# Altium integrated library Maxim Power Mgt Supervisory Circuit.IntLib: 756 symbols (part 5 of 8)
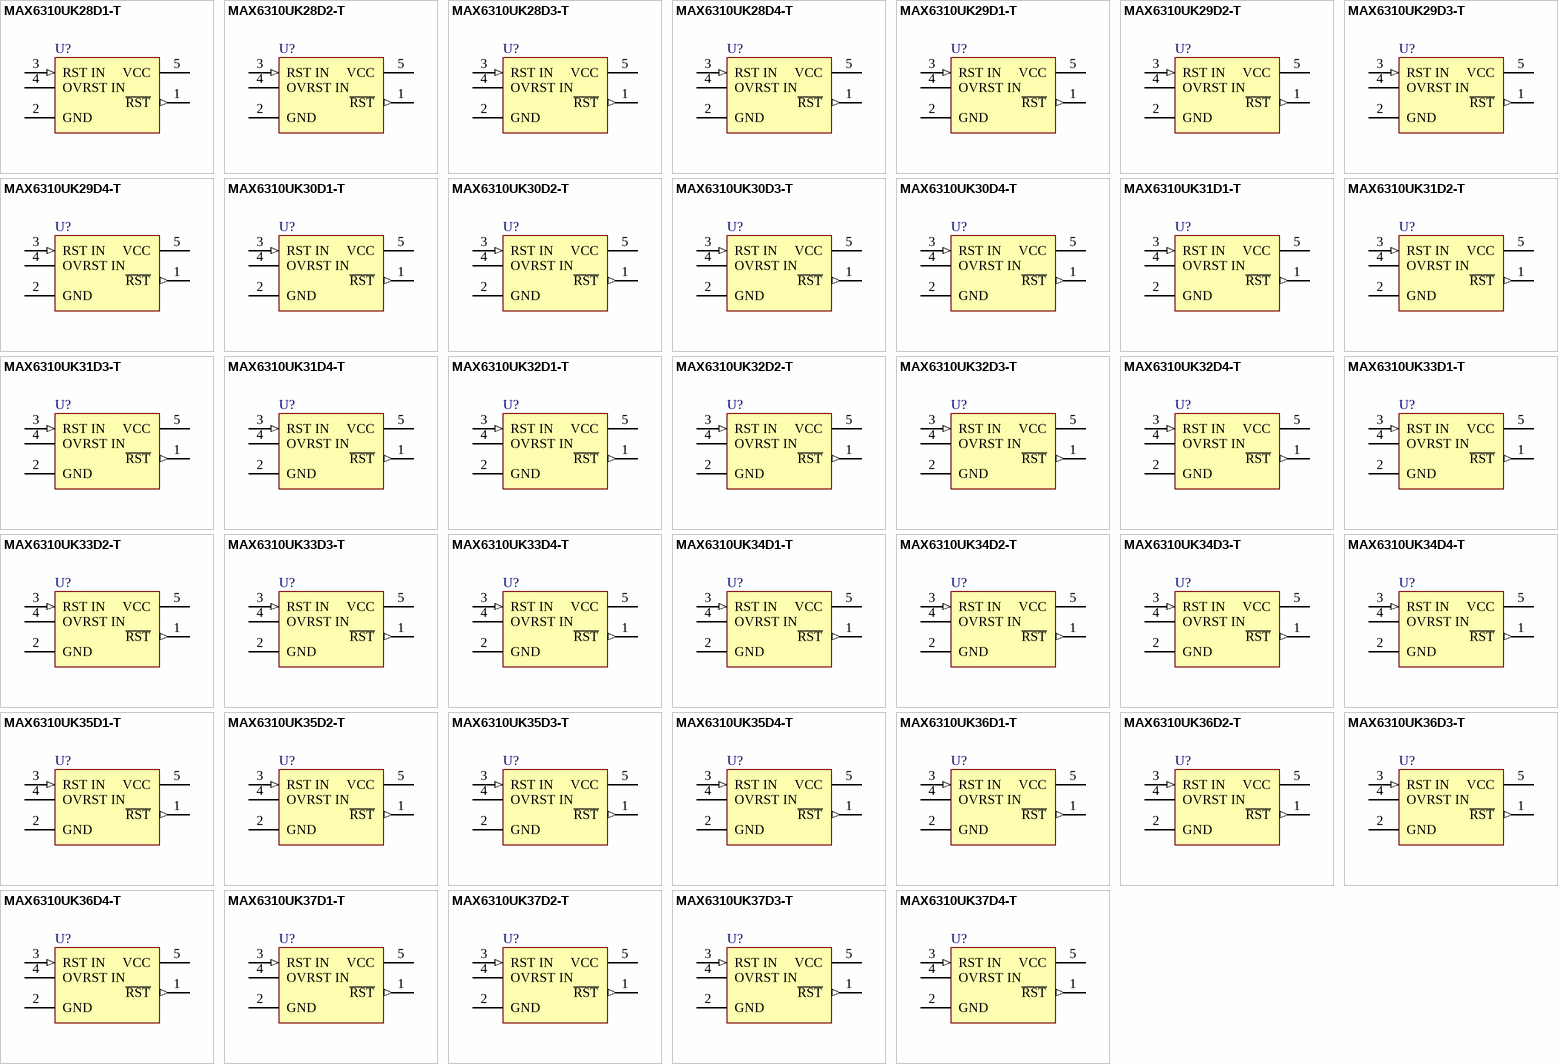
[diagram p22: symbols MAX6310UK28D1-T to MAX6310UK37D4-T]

## MAX6310UK36D1-T
designator U?
5-Pin, Multiple-Input, Programmable Reset IC
footprint SOT23-5_N (SOT23, 5-Leads, Body 2.9x1.6mm, Pitch 0.95mm, Lead Span 2.8mm, IPC Medium Density)
footprint SOT23-5_L (SOT23, 5-Leads, Body 2.9x1.6mm, Pitch 0.95mm, Lead Span 2.8mm, IPC High Density)
footprint SOT23-5_M (SOT23, 5-Leads, Body 2.9x1.6mm, Pitch 0.95mm, Lead Span 2.8mm, IPC Low Density)
pins: 1 ~{RST} (out), 2 GND (power), 3 RST IN (in), 4 OVRST IN, 5 VCC (power)

## MAX6310UK36D2-T
designator U?
5-Pin, Multiple-Input, Programmable Reset IC
footprint SOT23-5_N (SOT23, 5-Leads, Body 2.9x1.6mm, Pitch 0.95mm, Lead Span 2.8mm, IPC Medium Density)
footprint SOT23-5_L (SOT23, 5-Leads, Body 2.9x1.6mm, Pitch 0.95mm, Lead Span 2.8mm, IPC High Density)
footprint SOT23-5_M (SOT23, 5-Leads, Body 2.9x1.6mm, Pitch 0.95mm, Lead Span 2.8mm, IPC Low Density)
pins: 1 ~{RST} (out), 2 GND (power), 3 RST IN (in), 4 OVRST IN, 5 VCC (power)

## MAX6310UK36D3-T
designator U?
5-Pin, Multiple-Input, Programmable Reset IC
footprint SOT23-5_N (SOT23, 5-Leads, Body 2.9x1.6mm, Pitch 0.95mm, Lead Span 2.8mm, IPC Medium Density)
footprint SOT23-5_L (SOT23, 5-Leads, Body 2.9x1.6mm, Pitch 0.95mm, Lead Span 2.8mm, IPC High Density)
footprint SOT23-5_M (SOT23, 5-Leads, Body 2.9x1.6mm, Pitch 0.95mm, Lead Span 2.8mm, IPC Low Density)
pins: 1 ~{RST} (out), 2 GND (power), 3 RST IN (in), 4 OVRST IN, 5 VCC (power)

## MAX6310UK36D4-T
designator U?
5-Pin, Multiple-Input, Programmable Reset IC
footprint SOT23-5_N (SOT23, 5-Leads, Body 2.9x1.6mm, Pitch 0.95mm, Lead Span 2.8mm, IPC Medium Density)
footprint SOT23-5_L (SOT23, 5-Leads, Body 2.9x1.6mm, Pitch 0.95mm, Lead Span 2.8mm, IPC High Density)
footprint SOT23-5_M (SOT23, 5-Leads, Body 2.9x1.6mm, Pitch 0.95mm, Lead Span 2.8mm, IPC Low Density)
pins: 1 ~{RST} (out), 2 GND (power), 3 RST IN (in), 4 OVRST IN, 5 VCC (power)

## MAX6310UK37D1-T
designator U?
5-Pin, Multiple-Input, Programmable Reset IC
footprint SOT23-5_N (SOT23, 5-Leads, Body 2.9x1.6mm, Pitch 0.95mm, Lead Span 2.8mm, IPC Medium Density)
footprint SOT23-5_L (SOT23, 5-Leads, Body 2.9x1.6mm, Pitch 0.95mm, Lead Span 2.8mm, IPC High Density)
footprint SOT23-5_M (SOT23, 5-Leads, Body 2.9x1.6mm, Pitch 0.95mm, Lead Span 2.8mm, IPC Low Density)
pins: 1 ~{RST} (out), 2 GND (power), 3 RST IN (in), 4 OVRST IN, 5 VCC (power)

## MAX6310UK37D2-T
designator U?
5-Pin, Multiple-Input, Programmable Reset IC
footprint SOT23-5_N (SOT23, 5-Leads, Body 2.9x1.6mm, Pitch 0.95mm, Lead Span 2.8mm, IPC Medium Density)
footprint SOT23-5_L (SOT23, 5-Leads, Body 2.9x1.6mm, Pitch 0.95mm, Lead Span 2.8mm, IPC High Density)
footprint SOT23-5_M (SOT23, 5-Leads, Body 2.9x1.6mm, Pitch 0.95mm, Lead Span 2.8mm, IPC Low Density)
pins: 1 ~{RST} (out), 2 GND (power), 3 RST IN (in), 4 OVRST IN, 5 VCC (power)

## MAX6310UK37D3-T
designator U?
5-Pin, Multiple-Input, Programmable Reset IC
footprint SOT23-5_N (SOT23, 5-Leads, Body 2.9x1.6mm, Pitch 0.95mm, Lead Span 2.8mm, IPC Medium Density)
footprint SOT23-5_L (SOT23, 5-Leads, Body 2.9x1.6mm, Pitch 0.95mm, Lead Span 2.8mm, IPC High Density)
footprint SOT23-5_M (SOT23, 5-Leads, Body 2.9x1.6mm, Pitch 0.95mm, Lead Span 2.8mm, IPC Low Density)
pins: 1 ~{RST} (out), 2 GND (power), 3 RST IN (in), 4 OVRST IN, 5 VCC (power)

## MAX6310UK37D4-T
designator U?
5-Pin, Multiple-Input, Programmable Reset IC
footprint SOT23-5_N (SOT23, 5-Leads, Body 2.9x1.6mm, Pitch 0.95mm, Lead Span 2.8mm, IPC Medium Density)
footprint SOT23-5_L (SOT23, 5-Leads, Body 2.9x1.6mm, Pitch 0.95mm, Lead Span 2.8mm, IPC High Density)
footprint SOT23-5_M (SOT23, 5-Leads, Body 2.9x1.6mm, Pitch 0.95mm, Lead Span 2.8mm, IPC Low Density)
pins: 1 ~{RST} (out), 2 GND (power), 3 RST IN (in), 4 OVRST IN, 5 VCC (power)

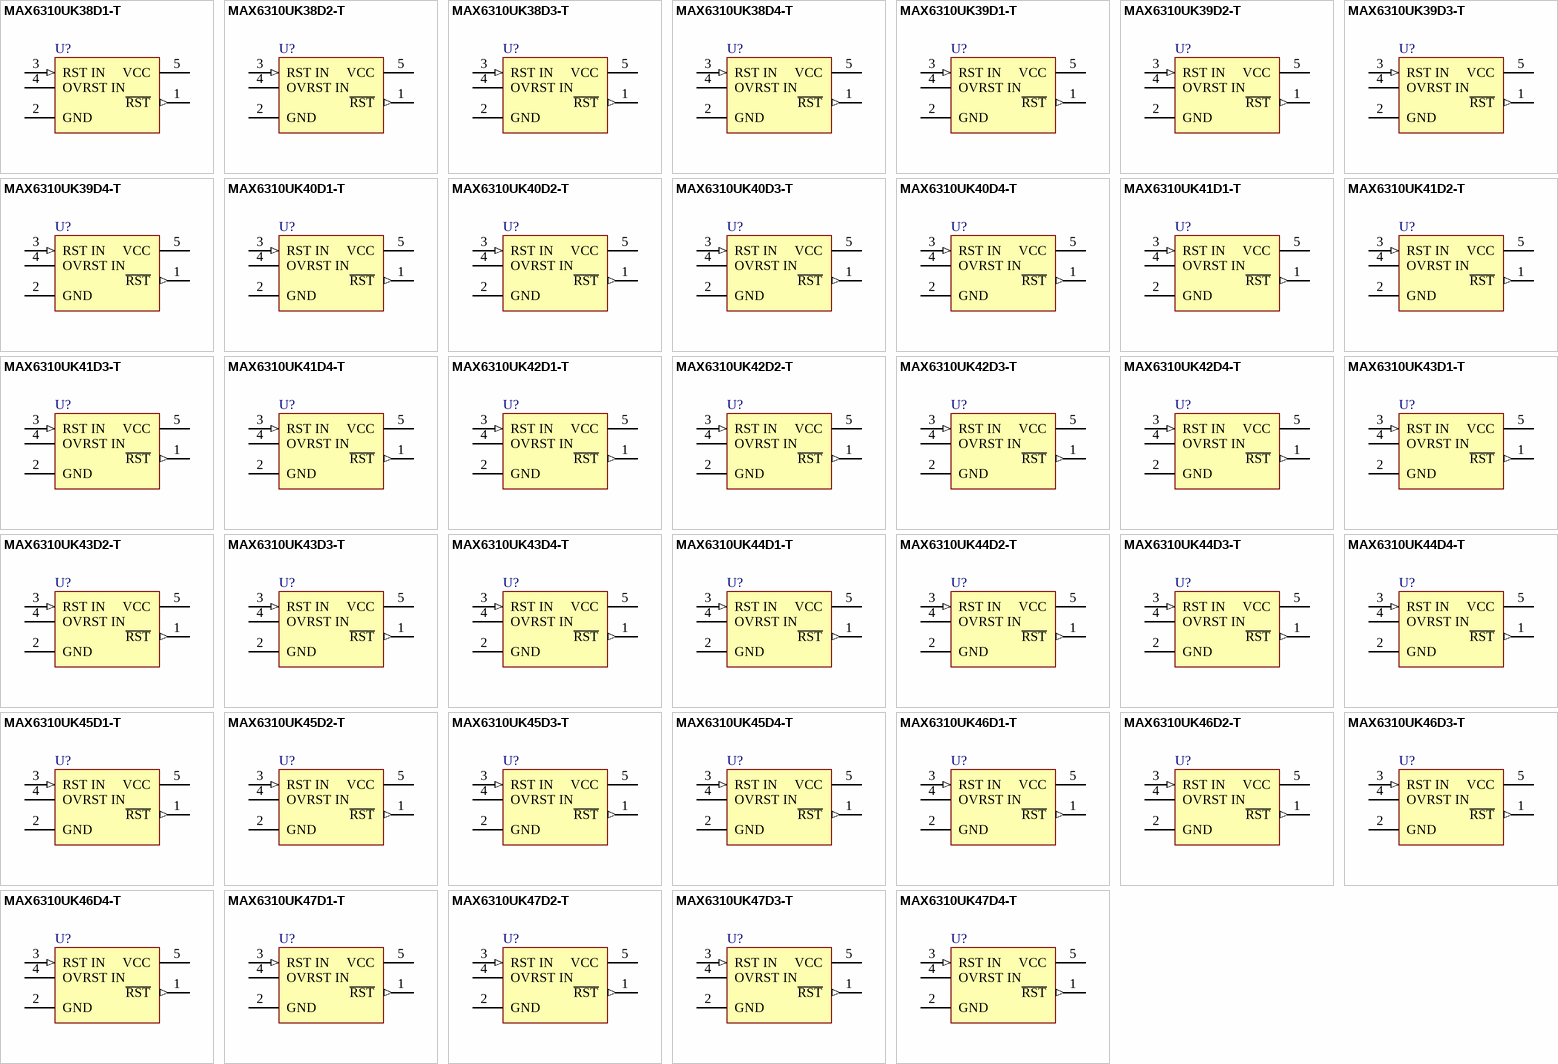
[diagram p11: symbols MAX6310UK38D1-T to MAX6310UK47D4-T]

## MAX6310UK38D1-T
designator U?
5-Pin, Multiple-Input, Programmable Reset IC
footprint SOT23-5_N (SOT23, 5-Leads, Body 2.9x1.6mm, Pitch 0.95mm, Lead Span 2.8mm, IPC Medium Density)
footprint SOT23-5_L (SOT23, 5-Leads, Body 2.9x1.6mm, Pitch 0.95mm, Lead Span 2.8mm, IPC High Density)
footprint SOT23-5_M (SOT23, 5-Leads, Body 2.9x1.6mm, Pitch 0.95mm, Lead Span 2.8mm, IPC Low Density)
pins: 1 ~{RST} (out), 2 GND (power), 3 RST IN (in), 4 OVRST IN, 5 VCC (power)

## MAX6310UK38D2-T
designator U?
5-Pin, Multiple-Input, Programmable Reset IC
footprint SOT23-5_N (SOT23, 5-Leads, Body 2.9x1.6mm, Pitch 0.95mm, Lead Span 2.8mm, IPC Medium Density)
footprint SOT23-5_L (SOT23, 5-Leads, Body 2.9x1.6mm, Pitch 0.95mm, Lead Span 2.8mm, IPC High Density)
footprint SOT23-5_M (SOT23, 5-Leads, Body 2.9x1.6mm, Pitch 0.95mm, Lead Span 2.8mm, IPC Low Density)
pins: 1 ~{RST} (out), 2 GND (power), 3 RST IN (in), 4 OVRST IN, 5 VCC (power)

## MAX6310UK38D3-T
designator U?
5-Pin, Multiple-Input, Programmable Reset IC
footprint SOT23-5_N (SOT23, 5-Leads, Body 2.9x1.6mm, Pitch 0.95mm, Lead Span 2.8mm, IPC Medium Density)
footprint SOT23-5_L (SOT23, 5-Leads, Body 2.9x1.6mm, Pitch 0.95mm, Lead Span 2.8mm, IPC High Density)
footprint SOT23-5_M (SOT23, 5-Leads, Body 2.9x1.6mm, Pitch 0.95mm, Lead Span 2.8mm, IPC Low Density)
pins: 1 ~{RST} (out), 2 GND (power), 3 RST IN (in), 4 OVRST IN, 5 VCC (power)

## MAX6310UK38D4-T
designator U?
5-Pin, Multiple-Input, Programmable Reset IC
footprint SOT23-5_N (SOT23, 5-Leads, Body 2.9x1.6mm, Pitch 0.95mm, Lead Span 2.8mm, IPC Medium Density)
footprint SOT23-5_L (SOT23, 5-Leads, Body 2.9x1.6mm, Pitch 0.95mm, Lead Span 2.8mm, IPC High Density)
footprint SOT23-5_M (SOT23, 5-Leads, Body 2.9x1.6mm, Pitch 0.95mm, Lead Span 2.8mm, IPC Low Density)
pins: 1 ~{RST} (out), 2 GND (power), 3 RST IN (in), 4 OVRST IN, 5 VCC (power)

## MAX6310UK39D1-T
designator U?
5-Pin, Multiple-Input, Programmable Reset IC
footprint SOT23-5_N (SOT23, 5-Leads, Body 2.9x1.6mm, Pitch 0.95mm, Lead Span 2.8mm, IPC Medium Density)
footprint SOT23-5_L (SOT23, 5-Leads, Body 2.9x1.6mm, Pitch 0.95mm, Lead Span 2.8mm, IPC High Density)
footprint SOT23-5_M (SOT23, 5-Leads, Body 2.9x1.6mm, Pitch 0.95mm, Lead Span 2.8mm, IPC Low Density)
pins: 1 ~{RST} (out), 2 GND (power), 3 RST IN (in), 4 OVRST IN, 5 VCC (power)

## MAX6310UK39D2-T
designator U?
5-Pin, Multiple-Input, Programmable Reset IC
footprint SOT23-5_N (SOT23, 5-Leads, Body 2.9x1.6mm, Pitch 0.95mm, Lead Span 2.8mm, IPC Medium Density)
footprint SOT23-5_L (SOT23, 5-Leads, Body 2.9x1.6mm, Pitch 0.95mm, Lead Span 2.8mm, IPC High Density)
footprint SOT23-5_M (SOT23, 5-Leads, Body 2.9x1.6mm, Pitch 0.95mm, Lead Span 2.8mm, IPC Low Density)
pins: 1 ~{RST} (out), 2 GND (power), 3 RST IN (in), 4 OVRST IN, 5 VCC (power)

## MAX6310UK39D3-T
designator U?
5-Pin, Multiple-Input, Programmable Reset IC
footprint SOT23-5_N (SOT23, 5-Leads, Body 2.9x1.6mm, Pitch 0.95mm, Lead Span 2.8mm, IPC Medium Density)
footprint SOT23-5_L (SOT23, 5-Leads, Body 2.9x1.6mm, Pitch 0.95mm, Lead Span 2.8mm, IPC High Density)
footprint SOT23-5_M (SOT23, 5-Leads, Body 2.9x1.6mm, Pitch 0.95mm, Lead Span 2.8mm, IPC Low Density)
pins: 1 ~{RST} (out), 2 GND (power), 3 RST IN (in), 4 OVRST IN, 5 VCC (power)

## MAX6310UK39D4-T
designator U?
5-Pin, Multiple-Input, Programmable Reset IC
footprint SOT23-5_N (SOT23, 5-Leads, Body 2.9x1.6mm, Pitch 0.95mm, Lead Span 2.8mm, IPC Medium Density)
footprint SOT23-5_L (SOT23, 5-Leads, Body 2.9x1.6mm, Pitch 0.95mm, Lead Span 2.8mm, IPC High Density)
footprint SOT23-5_M (SOT23, 5-Leads, Body 2.9x1.6mm, Pitch 0.95mm, Lead Span 2.8mm, IPC Low Density)
pins: 1 ~{RST} (out), 2 GND (power), 3 RST IN (in), 4 OVRST IN, 5 VCC (power)

## MAX6310UK40D1-T
designator U?
5-Pin, Multiple-Input, Programmable Reset IC
footprint SOT23-5_N (SOT23, 5-Leads, Body 2.9x1.6mm, Pitch 0.95mm, Lead Span 2.8mm, IPC Medium Density)
footprint SOT23-5_L (SOT23, 5-Leads, Body 2.9x1.6mm, Pitch 0.95mm, Lead Span 2.8mm, IPC High Density)
footprint SOT23-5_M (SOT23, 5-Leads, Body 2.9x1.6mm, Pitch 0.95mm, Lead Span 2.8mm, IPC Low Density)
pins: 1 ~{RST} (out), 2 GND (power), 3 RST IN (in), 4 OVRST IN, 5 VCC (power)

## MAX6310UK40D2-T
designator U?
5-Pin, Multiple-Input, Programmable Reset IC
footprint SOT23-5_N (SOT23, 5-Leads, Body 2.9x1.6mm, Pitch 0.95mm, Lead Span 2.8mm, IPC Medium Density)
footprint SOT23-5_L (SOT23, 5-Leads, Body 2.9x1.6mm, Pitch 0.95mm, Lead Span 2.8mm, IPC High Density)
footprint SOT23-5_M (SOT23, 5-Leads, Body 2.9x1.6mm, Pitch 0.95mm, Lead Span 2.8mm, IPC Low Density)
pins: 1 ~{RST} (out), 2 GND (power), 3 RST IN (in), 4 OVRST IN, 5 VCC (power)

## MAX6310UK40D3-T
designator U?
5-Pin, Multiple-Input, Programmable Reset IC
footprint SOT23-5_N (SOT23, 5-Leads, Body 2.9x1.6mm, Pitch 0.95mm, Lead Span 2.8mm, IPC Medium Density)
footprint SOT23-5_L (SOT23, 5-Leads, Body 2.9x1.6mm, Pitch 0.95mm, Lead Span 2.8mm, IPC High Density)
footprint SOT23-5_M (SOT23, 5-Leads, Body 2.9x1.6mm, Pitch 0.95mm, Lead Span 2.8mm, IPC Low Density)
pins: 1 ~{RST} (out), 2 GND (power), 3 RST IN (in), 4 OVRST IN, 5 VCC (power)

## MAX6310UK40D4-T
designator U?
5-Pin, Multiple-Input, Programmable Reset IC
footprint SOT23-5_N (SOT23, 5-Leads, Body 2.9x1.6mm, Pitch 0.95mm, Lead Span 2.8mm, IPC Medium Density)
footprint SOT23-5_L (SOT23, 5-Leads, Body 2.9x1.6mm, Pitch 0.95mm, Lead Span 2.8mm, IPC High Density)
footprint SOT23-5_M (SOT23, 5-Leads, Body 2.9x1.6mm, Pitch 0.95mm, Lead Span 2.8mm, IPC Low Density)
pins: 1 ~{RST} (out), 2 GND (power), 3 RST IN (in), 4 OVRST IN, 5 VCC (power)

## MAX6310UK41D1-T
designator U?
5-Pin, Multiple-Input, Programmable Reset IC
footprint SOT23-5_N (SOT23, 5-Leads, Body 2.9x1.6mm, Pitch 0.95mm, Lead Span 2.8mm, IPC Medium Density)
footprint SOT23-5_L (SOT23, 5-Leads, Body 2.9x1.6mm, Pitch 0.95mm, Lead Span 2.8mm, IPC High Density)
footprint SOT23-5_M (SOT23, 5-Leads, Body 2.9x1.6mm, Pitch 0.95mm, Lead Span 2.8mm, IPC Low Density)
pins: 1 ~{RST} (out), 2 GND (power), 3 RST IN (in), 4 OVRST IN, 5 VCC (power)

## MAX6310UK41D2-T
designator U?
5-Pin, Multiple-Input, Programmable Reset IC
footprint SOT23-5_N (SOT23, 5-Leads, Body 2.9x1.6mm, Pitch 0.95mm, Lead Span 2.8mm, IPC Medium Density)
footprint SOT23-5_L (SOT23, 5-Leads, Body 2.9x1.6mm, Pitch 0.95mm, Lead Span 2.8mm, IPC High Density)
footprint SOT23-5_M (SOT23, 5-Leads, Body 2.9x1.6mm, Pitch 0.95mm, Lead Span 2.8mm, IPC Low Density)
pins: 1 ~{RST} (out), 2 GND (power), 3 RST IN (in), 4 OVRST IN, 5 VCC (power)

## MAX6310UK41D3-T
designator U?
5-Pin, Multiple-Input, Programmable Reset IC
footprint SOT23-5_N (SOT23, 5-Leads, Body 2.9x1.6mm, Pitch 0.95mm, Lead Span 2.8mm, IPC Medium Density)
footprint SOT23-5_L (SOT23, 5-Leads, Body 2.9x1.6mm, Pitch 0.95mm, Lead Span 2.8mm, IPC High Density)
footprint SOT23-5_M (SOT23, 5-Leads, Body 2.9x1.6mm, Pitch 0.95mm, Lead Span 2.8mm, IPC Low Density)
pins: 1 ~{RST} (out), 2 GND (power), 3 RST IN (in), 4 OVRST IN, 5 VCC (power)

## MAX6310UK41D4-T
designator U?
5-Pin, Multiple-Input, Programmable Reset IC
footprint SOT23-5_N (SOT23, 5-Leads, Body 2.9x1.6mm, Pitch 0.95mm, Lead Span 2.8mm, IPC Medium Density)
footprint SOT23-5_L (SOT23, 5-Leads, Body 2.9x1.6mm, Pitch 0.95mm, Lead Span 2.8mm, IPC High Density)
footprint SOT23-5_M (SOT23, 5-Leads, Body 2.9x1.6mm, Pitch 0.95mm, Lead Span 2.8mm, IPC Low Density)
pins: 1 ~{RST} (out), 2 GND (power), 3 RST IN (in), 4 OVRST IN, 5 VCC (power)

## MAX6310UK42D1-T
designator U?
5-Pin, Multiple-Input, Programmable Reset IC
footprint SOT23-5_N (SOT23, 5-Leads, Body 2.9x1.6mm, Pitch 0.95mm, Lead Span 2.8mm, IPC Medium Density)
footprint SOT23-5_L (SOT23, 5-Leads, Body 2.9x1.6mm, Pitch 0.95mm, Lead Span 2.8mm, IPC High Density)
footprint SOT23-5_M (SOT23, 5-Leads, Body 2.9x1.6mm, Pitch 0.95mm, Lead Span 2.8mm, IPC Low Density)
pins: 1 ~{RST} (out), 2 GND (power), 3 RST IN (in), 4 OVRST IN, 5 VCC (power)

## MAX6310UK42D2-T
designator U?
5-Pin, Multiple-Input, Programmable Reset IC
footprint SOT23-5_N (SOT23, 5-Leads, Body 2.9x1.6mm, Pitch 0.95mm, Lead Span 2.8mm, IPC Medium Density)
footprint SOT23-5_L (SOT23, 5-Leads, Body 2.9x1.6mm, Pitch 0.95mm, Lead Span 2.8mm, IPC High Density)
footprint SOT23-5_M (SOT23, 5-Leads, Body 2.9x1.6mm, Pitch 0.95mm, Lead Span 2.8mm, IPC Low Density)
pins: 1 ~{RST} (out), 2 GND (power), 3 RST IN (in), 4 OVRST IN, 5 VCC (power)

## MAX6310UK42D3-T
designator U?
5-Pin, Multiple-Input, Programmable Reset IC
footprint SOT23-5_N (SOT23, 5-Leads, Body 2.9x1.6mm, Pitch 0.95mm, Lead Span 2.8mm, IPC Medium Density)
footprint SOT23-5_L (SOT23, 5-Leads, Body 2.9x1.6mm, Pitch 0.95mm, Lead Span 2.8mm, IPC High Density)
footprint SOT23-5_M (SOT23, 5-Leads, Body 2.9x1.6mm, Pitch 0.95mm, Lead Span 2.8mm, IPC Low Density)
pins: 1 ~{RST} (out), 2 GND (power), 3 RST IN (in), 4 OVRST IN, 5 VCC (power)

## MAX6310UK42D4-T
designator U?
5-Pin, Multiple-Input, Programmable Reset IC
footprint SOT23-5_N (SOT23, 5-Leads, Body 2.9x1.6mm, Pitch 0.95mm, Lead Span 2.8mm, IPC Medium Density)
footprint SOT23-5_L (SOT23, 5-Leads, Body 2.9x1.6mm, Pitch 0.95mm, Lead Span 2.8mm, IPC High Density)
footprint SOT23-5_M (SOT23, 5-Leads, Body 2.9x1.6mm, Pitch 0.95mm, Lead Span 2.8mm, IPC Low Density)
pins: 1 ~{RST} (out), 2 GND (power), 3 RST IN (in), 4 OVRST IN, 5 VCC (power)

## MAX6310UK43D1-T
designator U?
5-Pin, Multiple-Input, Programmable Reset IC
footprint SOT23-5_N (SOT23, 5-Leads, Body 2.9x1.6mm, Pitch 0.95mm, Lead Span 2.8mm, IPC Medium Density)
footprint SOT23-5_L (SOT23, 5-Leads, Body 2.9x1.6mm, Pitch 0.95mm, Lead Span 2.8mm, IPC High Density)
footprint SOT23-5_M (SOT23, 5-Leads, Body 2.9x1.6mm, Pitch 0.95mm, Lead Span 2.8mm, IPC Low Density)
pins: 1 ~{RST} (out), 2 GND (power), 3 RST IN (in), 4 OVRST IN, 5 VCC (power)

## MAX6310UK43D2-T
designator U?
5-Pin, Multiple-Input, Programmable Reset IC
footprint SOT23-5_N (SOT23, 5-Leads, Body 2.9x1.6mm, Pitch 0.95mm, Lead Span 2.8mm, IPC Medium Density)
footprint SOT23-5_L (SOT23, 5-Leads, Body 2.9x1.6mm, Pitch 0.95mm, Lead Span 2.8mm, IPC High Density)
footprint SOT23-5_M (SOT23, 5-Leads, Body 2.9x1.6mm, Pitch 0.95mm, Lead Span 2.8mm, IPC Low Density)
pins: 1 ~{RST} (out), 2 GND (power), 3 RST IN (in), 4 OVRST IN, 5 VCC (power)

## MAX6310UK43D3-T
designator U?
5-Pin, Multiple-Input, Programmable Reset IC
footprint SOT23-5_N (SOT23, 5-Leads, Body 2.9x1.6mm, Pitch 0.95mm, Lead Span 2.8mm, IPC Medium Density)
footprint SOT23-5_L (SOT23, 5-Leads, Body 2.9x1.6mm, Pitch 0.95mm, Lead Span 2.8mm, IPC High Density)
footprint SOT23-5_M (SOT23, 5-Leads, Body 2.9x1.6mm, Pitch 0.95mm, Lead Span 2.8mm, IPC Low Density)
pins: 1 ~{RST} (out), 2 GND (power), 3 RST IN (in), 4 OVRST IN, 5 VCC (power)

## MAX6310UK43D4-T
designator U?
5-Pin, Multiple-Input, Programmable Reset IC
footprint SOT23-5_N (SOT23, 5-Leads, Body 2.9x1.6mm, Pitch 0.95mm, Lead Span 2.8mm, IPC Medium Density)
footprint SOT23-5_L (SOT23, 5-Leads, Body 2.9x1.6mm, Pitch 0.95mm, Lead Span 2.8mm, IPC High Density)
footprint SOT23-5_M (SOT23, 5-Leads, Body 2.9x1.6mm, Pitch 0.95mm, Lead Span 2.8mm, IPC Low Density)
pins: 1 ~{RST} (out), 2 GND (power), 3 RST IN (in), 4 OVRST IN, 5 VCC (power)

## MAX6310UK44D1-T
designator U?
5-Pin, Multiple-Input, Programmable Reset IC
footprint SOT23-5_N (SOT23, 5-Leads, Body 2.9x1.6mm, Pitch 0.95mm, Lead Span 2.8mm, IPC Medium Density)
footprint SOT23-5_L (SOT23, 5-Leads, Body 2.9x1.6mm, Pitch 0.95mm, Lead Span 2.8mm, IPC High Density)
footprint SOT23-5_M (SOT23, 5-Leads, Body 2.9x1.6mm, Pitch 0.95mm, Lead Span 2.8mm, IPC Low Density)
pins: 1 ~{RST} (out), 2 GND (power), 3 RST IN (in), 4 OVRST IN, 5 VCC (power)

## MAX6310UK44D2-T
designator U?
5-Pin, Multiple-Input, Programmable Reset IC
footprint SOT23-5_N (SOT23, 5-Leads, Body 2.9x1.6mm, Pitch 0.95mm, Lead Span 2.8mm, IPC Medium Density)
footprint SOT23-5_L (SOT23, 5-Leads, Body 2.9x1.6mm, Pitch 0.95mm, Lead Span 2.8mm, IPC High Density)
footprint SOT23-5_M (SOT23, 5-Leads, Body 2.9x1.6mm, Pitch 0.95mm, Lead Span 2.8mm, IPC Low Density)
pins: 1 ~{RST} (out), 2 GND (power), 3 RST IN (in), 4 OVRST IN, 5 VCC (power)

## MAX6310UK44D3-T
designator U?
5-Pin, Multiple-Input, Programmable Reset IC
footprint SOT23-5_N (SOT23, 5-Leads, Body 2.9x1.6mm, Pitch 0.95mm, Lead Span 2.8mm, IPC Medium Density)
footprint SOT23-5_L (SOT23, 5-Leads, Body 2.9x1.6mm, Pitch 0.95mm, Lead Span 2.8mm, IPC High Density)
footprint SOT23-5_M (SOT23, 5-Leads, Body 2.9x1.6mm, Pitch 0.95mm, Lead Span 2.8mm, IPC Low Density)
pins: 1 ~{RST} (out), 2 GND (power), 3 RST IN (in), 4 OVRST IN, 5 VCC (power)

## MAX6310UK44D4-T
designator U?
5-Pin, Multiple-Input, Programmable Reset IC
footprint SOT23-5_N (SOT23, 5-Leads, Body 2.9x1.6mm, Pitch 0.95mm, Lead Span 2.8mm, IPC Medium Density)
footprint SOT23-5_L (SOT23, 5-Leads, Body 2.9x1.6mm, Pitch 0.95mm, Lead Span 2.8mm, IPC High Density)
footprint SOT23-5_M (SOT23, 5-Leads, Body 2.9x1.6mm, Pitch 0.95mm, Lead Span 2.8mm, IPC Low Density)
pins: 1 ~{RST} (out), 2 GND (power), 3 RST IN (in), 4 OVRST IN, 5 VCC (power)

## MAX6310UK45D1-T
designator U?
5-Pin, Multiple-Input, Programmable Reset IC
footprint SOT23-5_N (SOT23, 5-Leads, Body 2.9x1.6mm, Pitch 0.95mm, Lead Span 2.8mm, IPC Medium Density)
footprint SOT23-5_L (SOT23, 5-Leads, Body 2.9x1.6mm, Pitch 0.95mm, Lead Span 2.8mm, IPC High Density)
footprint SOT23-5_M (SOT23, 5-Leads, Body 2.9x1.6mm, Pitch 0.95mm, Lead Span 2.8mm, IPC Low Density)
pins: 1 ~{RST} (out), 2 GND (power), 3 RST IN (in), 4 OVRST IN, 5 VCC (power)

## MAX6310UK45D2-T
designator U?
5-Pin, Multiple-Input, Programmable Reset IC
footprint SOT23-5_N (SOT23, 5-Leads, Body 2.9x1.6mm, Pitch 0.95mm, Lead Span 2.8mm, IPC Medium Density)
footprint SOT23-5_L (SOT23, 5-Leads, Body 2.9x1.6mm, Pitch 0.95mm, Lead Span 2.8mm, IPC High Density)
footprint SOT23-5_M (SOT23, 5-Leads, Body 2.9x1.6mm, Pitch 0.95mm, Lead Span 2.8mm, IPC Low Density)
pins: 1 ~{RST} (out), 2 GND (power), 3 RST IN (in), 4 OVRST IN, 5 VCC (power)

## MAX6310UK45D3-T
designator U?
5-Pin, Multiple-Input, Programmable Reset IC
footprint SOT23-5_N (SOT23, 5-Leads, Body 2.9x1.6mm, Pitch 0.95mm, Lead Span 2.8mm, IPC Medium Density)
footprint SOT23-5_L (SOT23, 5-Leads, Body 2.9x1.6mm, Pitch 0.95mm, Lead Span 2.8mm, IPC High Density)
footprint SOT23-5_M (SOT23, 5-Leads, Body 2.9x1.6mm, Pitch 0.95mm, Lead Span 2.8mm, IPC Low Density)
pins: 1 ~{RST} (out), 2 GND (power), 3 RST IN (in), 4 OVRST IN, 5 VCC (power)

## MAX6310UK45D4-T
designator U?
5-Pin, Multiple-Input, Programmable Reset IC
footprint SOT23-5_N (SOT23, 5-Leads, Body 2.9x1.6mm, Pitch 0.95mm, Lead Span 2.8mm, IPC Medium Density)
footprint SOT23-5_L (SOT23, 5-Leads, Body 2.9x1.6mm, Pitch 0.95mm, Lead Span 2.8mm, IPC High Density)
footprint SOT23-5_M (SOT23, 5-Leads, Body 2.9x1.6mm, Pitch 0.95mm, Lead Span 2.8mm, IPC Low Density)
pins: 1 ~{RST} (out), 2 GND (power), 3 RST IN (in), 4 OVRST IN, 5 VCC (power)

## MAX6310UK46D1-T
designator U?
5-Pin, Multiple-Input, Programmable Reset IC
footprint SOT23-5_N (SOT23, 5-Leads, Body 2.9x1.6mm, Pitch 0.95mm, Lead Span 2.8mm, IPC Medium Density)
footprint SOT23-5_L (SOT23, 5-Leads, Body 2.9x1.6mm, Pitch 0.95mm, Lead Span 2.8mm, IPC High Density)
footprint SOT23-5_M (SOT23, 5-Leads, Body 2.9x1.6mm, Pitch 0.95mm, Lead Span 2.8mm, IPC Low Density)
pins: 1 ~{RST} (out), 2 GND (power), 3 RST IN (in), 4 OVRST IN, 5 VCC (power)

## MAX6310UK46D2-T
designator U?
5-Pin, Multiple-Input, Programmable Reset IC
footprint SOT23-5_N (SOT23, 5-Leads, Body 2.9x1.6mm, Pitch 0.95mm, Lead Span 2.8mm, IPC Medium Density)
footprint SOT23-5_L (SOT23, 5-Leads, Body 2.9x1.6mm, Pitch 0.95mm, Lead Span 2.8mm, IPC High Density)
footprint SOT23-5_M (SOT23, 5-Leads, Body 2.9x1.6mm, Pitch 0.95mm, Lead Span 2.8mm, IPC Low Density)
pins: 1 ~{RST} (out), 2 GND (power), 3 RST IN (in), 4 OVRST IN, 5 VCC (power)

## MAX6310UK46D3-T
designator U?
5-Pin, Multiple-Input, Programmable Reset IC
footprint SOT23-5_N (SOT23, 5-Leads, Body 2.9x1.6mm, Pitch 0.95mm, Lead Span 2.8mm, IPC Medium Density)
footprint SOT23-5_L (SOT23, 5-Leads, Body 2.9x1.6mm, Pitch 0.95mm, Lead Span 2.8mm, IPC High Density)
footprint SOT23-5_M (SOT23, 5-Leads, Body 2.9x1.6mm, Pitch 0.95mm, Lead Span 2.8mm, IPC Low Density)
pins: 1 ~{RST} (out), 2 GND (power), 3 RST IN (in), 4 OVRST IN, 5 VCC (power)

## MAX6310UK46D4-T
designator U?
5-Pin, Multiple-Input, Programmable Reset IC
footprint SOT23-5_N (SOT23, 5-Leads, Body 2.9x1.6mm, Pitch 0.95mm, Lead Span 2.8mm, IPC Medium Density)
footprint SOT23-5_L (SOT23, 5-Leads, Body 2.9x1.6mm, Pitch 0.95mm, Lead Span 2.8mm, IPC High Density)
footprint SOT23-5_M (SOT23, 5-Leads, Body 2.9x1.6mm, Pitch 0.95mm, Lead Span 2.8mm, IPC Low Density)
pins: 1 ~{RST} (out), 2 GND (power), 3 RST IN (in), 4 OVRST IN, 5 VCC (power)

## MAX6310UK47D1-T
designator U?
5-Pin, Multiple-Input, Programmable Reset IC
footprint SOT23-5_N (SOT23, 5-Leads, Body 2.9x1.6mm, Pitch 0.95mm, Lead Span 2.8mm, IPC Medium Density)
footprint SOT23-5_L (SOT23, 5-Leads, Body 2.9x1.6mm, Pitch 0.95mm, Lead Span 2.8mm, IPC High Density)
footprint SOT23-5_M (SOT23, 5-Leads, Body 2.9x1.6mm, Pitch 0.95mm, Lead Span 2.8mm, IPC Low Density)
pins: 1 ~{RST} (out), 2 GND (power), 3 RST IN (in), 4 OVRST IN, 5 VCC (power)

## MAX6310UK47D2-T
designator U?
5-Pin, Multiple-Input, Programmable Reset IC
footprint SOT23-5_N (SOT23, 5-Leads, Body 2.9x1.6mm, Pitch 0.95mm, Lead Span 2.8mm, IPC Medium Density)
footprint SOT23-5_L (SOT23, 5-Leads, Body 2.9x1.6mm, Pitch 0.95mm, Lead Span 2.8mm, IPC High Density)
footprint SOT23-5_M (SOT23, 5-Leads, Body 2.9x1.6mm, Pitch 0.95mm, Lead Span 2.8mm, IPC Low Density)
pins: 1 ~{RST} (out), 2 GND (power), 3 RST IN (in), 4 OVRST IN, 5 VCC (power)

## MAX6310UK47D3-T
designator U?
5-Pin, Multiple-Input, Programmable Reset IC
footprint SOT23-5_N (SOT23, 5-Leads, Body 2.9x1.6mm, Pitch 0.95mm, Lead Span 2.8mm, IPC Medium Density)
footprint SOT23-5_L (SOT23, 5-Leads, Body 2.9x1.6mm, Pitch 0.95mm, Lead Span 2.8mm, IPC High Density)
footprint SOT23-5_M (SOT23, 5-Leads, Body 2.9x1.6mm, Pitch 0.95mm, Lead Span 2.8mm, IPC Low Density)
pins: 1 ~{RST} (out), 2 GND (power), 3 RST IN (in), 4 OVRST IN, 5 VCC (power)

## MAX6310UK47D4-T
designator U?
5-Pin, Multiple-Input, Programmable Reset IC
footprint SOT23-5_N (SOT23, 5-Leads, Body 2.9x1.6mm, Pitch 0.95mm, Lead Span 2.8mm, IPC Medium Density)
footprint SOT23-5_L (SOT23, 5-Leads, Body 2.9x1.6mm, Pitch 0.95mm, Lead Span 2.8mm, IPC High Density)
footprint SOT23-5_M (SOT23, 5-Leads, Body 2.9x1.6mm, Pitch 0.95mm, Lead Span 2.8mm, IPC Low Density)
pins: 1 ~{RST} (out), 2 GND (power), 3 RST IN (in), 4 OVRST IN, 5 VCC (power)

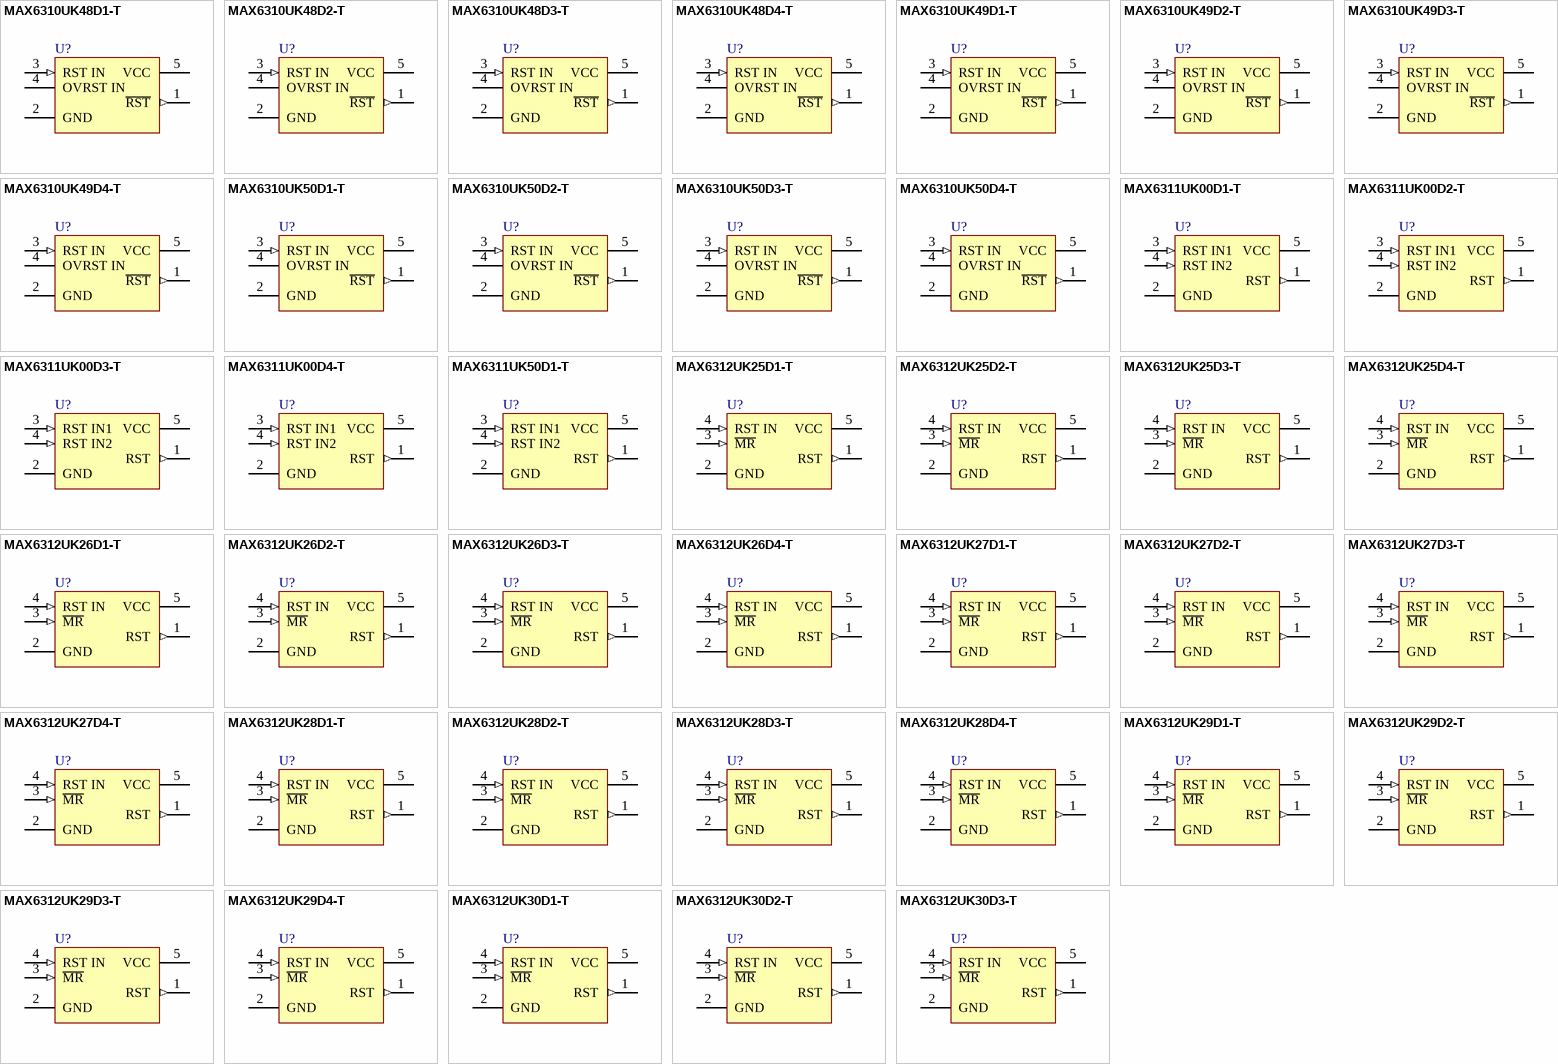
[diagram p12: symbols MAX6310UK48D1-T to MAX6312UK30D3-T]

## MAX6310UK48D1-T
designator U?
5-Pin, Multiple-Input, Programmable Reset IC
footprint SOT23-5_N (SOT23, 5-Leads, Body 2.9x1.6mm, Pitch 0.95mm, Lead Span 2.8mm, IPC Medium Density)
footprint SOT23-5_L (SOT23, 5-Leads, Body 2.9x1.6mm, Pitch 0.95mm, Lead Span 2.8mm, IPC High Density)
footprint SOT23-5_M (SOT23, 5-Leads, Body 2.9x1.6mm, Pitch 0.95mm, Lead Span 2.8mm, IPC Low Density)
pins: 1 ~{RST} (out), 2 GND (power), 3 RST IN (in), 4 OVRST IN, 5 VCC (power)

## MAX6310UK48D2-T
designator U?
5-Pin, Multiple-Input, Programmable Reset IC
footprint SOT23-5_N (SOT23, 5-Leads, Body 2.9x1.6mm, Pitch 0.95mm, Lead Span 2.8mm, IPC Medium Density)
footprint SOT23-5_L (SOT23, 5-Leads, Body 2.9x1.6mm, Pitch 0.95mm, Lead Span 2.8mm, IPC High Density)
footprint SOT23-5_M (SOT23, 5-Leads, Body 2.9x1.6mm, Pitch 0.95mm, Lead Span 2.8mm, IPC Low Density)
pins: 1 ~{RST} (out), 2 GND (power), 3 RST IN (in), 4 OVRST IN, 5 VCC (power)

## MAX6310UK48D3-T
designator U?
5-Pin, Multiple-Input, Programmable Reset IC
footprint SOT23-5_N (SOT23, 5-Leads, Body 2.9x1.6mm, Pitch 0.95mm, Lead Span 2.8mm, IPC Medium Density)
footprint SOT23-5_L (SOT23, 5-Leads, Body 2.9x1.6mm, Pitch 0.95mm, Lead Span 2.8mm, IPC High Density)
footprint SOT23-5_M (SOT23, 5-Leads, Body 2.9x1.6mm, Pitch 0.95mm, Lead Span 2.8mm, IPC Low Density)
pins: 1 ~{RST} (out), 2 GND (power), 3 RST IN (in), 4 OVRST IN, 5 VCC (power)

## MAX6310UK48D4-T
designator U?
5-Pin, Multiple-Input, Programmable Reset IC
footprint SOT23-5_N (SOT23, 5-Leads, Body 2.9x1.6mm, Pitch 0.95mm, Lead Span 2.8mm, IPC Medium Density)
footprint SOT23-5_L (SOT23, 5-Leads, Body 2.9x1.6mm, Pitch 0.95mm, Lead Span 2.8mm, IPC High Density)
footprint SOT23-5_M (SOT23, 5-Leads, Body 2.9x1.6mm, Pitch 0.95mm, Lead Span 2.8mm, IPC Low Density)
pins: 1 ~{RST} (out), 2 GND (power), 3 RST IN (in), 4 OVRST IN, 5 VCC (power)

## MAX6310UK49D1-T
designator U?
5-Pin, Multiple-Input, Programmable Reset IC
footprint SOT23-5_N (SOT23, 5-Leads, Body 2.9x1.6mm, Pitch 0.95mm, Lead Span 2.8mm, IPC Medium Density)
footprint SOT23-5_L (SOT23, 5-Leads, Body 2.9x1.6mm, Pitch 0.95mm, Lead Span 2.8mm, IPC High Density)
footprint SOT23-5_M (SOT23, 5-Leads, Body 2.9x1.6mm, Pitch 0.95mm, Lead Span 2.8mm, IPC Low Density)
pins: 1 ~{RST} (out), 2 GND (power), 3 RST IN (in), 4 OVRST IN, 5 VCC (power)

## MAX6310UK49D2-T
designator U?
5-Pin, Multiple-Input, Programmable Reset IC
footprint SOT23-5_N (SOT23, 5-Leads, Body 2.9x1.6mm, Pitch 0.95mm, Lead Span 2.8mm, IPC Medium Density)
footprint SOT23-5_L (SOT23, 5-Leads, Body 2.9x1.6mm, Pitch 0.95mm, Lead Span 2.8mm, IPC High Density)
footprint SOT23-5_M (SOT23, 5-Leads, Body 2.9x1.6mm, Pitch 0.95mm, Lead Span 2.8mm, IPC Low Density)
pins: 1 ~{RST} (out), 2 GND (power), 3 RST IN (in), 4 OVRST IN, 5 VCC (power)

## MAX6310UK49D3-T
designator U?
5-Pin, Multiple-Input, Programmable Reset IC
footprint SOT23-5_N (SOT23, 5-Leads, Body 2.9x1.6mm, Pitch 0.95mm, Lead Span 2.8mm, IPC Medium Density)
footprint SOT23-5_L (SOT23, 5-Leads, Body 2.9x1.6mm, Pitch 0.95mm, Lead Span 2.8mm, IPC High Density)
footprint SOT23-5_M (SOT23, 5-Leads, Body 2.9x1.6mm, Pitch 0.95mm, Lead Span 2.8mm, IPC Low Density)
pins: 1 ~{RST} (out), 2 GND (power), 3 RST IN (in), 4 OVRST IN, 5 VCC (power)

## MAX6310UK49D4-T
designator U?
5-Pin, Multiple-Input, Programmable Reset IC
footprint SOT23-5_N (SOT23, 5-Leads, Body 2.9x1.6mm, Pitch 0.95mm, Lead Span 2.8mm, IPC Medium Density)
footprint SOT23-5_L (SOT23, 5-Leads, Body 2.9x1.6mm, Pitch 0.95mm, Lead Span 2.8mm, IPC High Density)
footprint SOT23-5_M (SOT23, 5-Leads, Body 2.9x1.6mm, Pitch 0.95mm, Lead Span 2.8mm, IPC Low Density)
pins: 1 ~{RST} (out), 2 GND (power), 3 RST IN (in), 4 OVRST IN, 5 VCC (power)

## MAX6310UK50D1-T
designator U?
5-Pin, Multiple-Input, Programmable Reset IC
footprint SOT23-5_N (SOT23, 5-Leads, Body 2.9x1.6mm, Pitch 0.95mm, Lead Span 2.8mm, IPC Medium Density)
footprint SOT23-5_L (SOT23, 5-Leads, Body 2.9x1.6mm, Pitch 0.95mm, Lead Span 2.8mm, IPC High Density)
footprint SOT23-5_M (SOT23, 5-Leads, Body 2.9x1.6mm, Pitch 0.95mm, Lead Span 2.8mm, IPC Low Density)
pins: 1 ~{RST} (out), 2 GND (power), 3 RST IN (in), 4 OVRST IN, 5 VCC (power)

## MAX6310UK50D2-T
designator U?
5-Pin, Multiple-Input, Programmable Reset IC
footprint SOT23-5_N (SOT23, 5-Leads, Body 2.9x1.6mm, Pitch 0.95mm, Lead Span 2.8mm, IPC Medium Density)
footprint SOT23-5_L (SOT23, 5-Leads, Body 2.9x1.6mm, Pitch 0.95mm, Lead Span 2.8mm, IPC High Density)
footprint SOT23-5_M (SOT23, 5-Leads, Body 2.9x1.6mm, Pitch 0.95mm, Lead Span 2.8mm, IPC Low Density)
pins: 1 ~{RST} (out), 2 GND (power), 3 RST IN (in), 4 OVRST IN, 5 VCC (power)

## MAX6310UK50D3-T
designator U?
5-Pin, Multiple-Input, Programmable Reset IC
footprint SOT23-5_N (SOT23, 5-Leads, Body 2.9x1.6mm, Pitch 0.95mm, Lead Span 2.8mm, IPC Medium Density)
footprint SOT23-5_L (SOT23, 5-Leads, Body 2.9x1.6mm, Pitch 0.95mm, Lead Span 2.8mm, IPC High Density)
footprint SOT23-5_M (SOT23, 5-Leads, Body 2.9x1.6mm, Pitch 0.95mm, Lead Span 2.8mm, IPC Low Density)
pins: 1 ~{RST} (out), 2 GND (power), 3 RST IN (in), 4 OVRST IN, 5 VCC (power)

## MAX6310UK50D4-T
designator U?
5-Pin, Multiple-Input, Programmable Reset IC
footprint SOT23-5_N (SOT23, 5-Leads, Body 2.9x1.6mm, Pitch 0.95mm, Lead Span 2.8mm, IPC Medium Density)
footprint SOT23-5_L (SOT23, 5-Leads, Body 2.9x1.6mm, Pitch 0.95mm, Lead Span 2.8mm, IPC High Density)
footprint SOT23-5_M (SOT23, 5-Leads, Body 2.9x1.6mm, Pitch 0.95mm, Lead Span 2.8mm, IPC Low Density)
pins: 1 ~{RST} (out), 2 GND (power), 3 RST IN (in), 4 OVRST IN, 5 VCC (power)

## MAX6311UK00D1-T
designator U?
5-Pin, Multiple-Input, Programmable Reset IC
footprint SOT23-5_N (SOT23, 5-Leads, Body 2.9x1.6mm, Pitch 0.95mm, Lead Span 2.8mm, IPC Medium Density)
footprint SOT23-5_L (SOT23, 5-Leads, Body 2.9x1.6mm, Pitch 0.95mm, Lead Span 2.8mm, IPC High Density)
footprint SOT23-5_M (SOT23, 5-Leads, Body 2.9x1.6mm, Pitch 0.95mm, Lead Span 2.8mm, IPC Low Density)
pins: 1 RST (out), 2 GND (power), 3 RST IN1 (in), 4 RST IN2 (in), 5 VCC (power)

## MAX6311UK00D2-T
designator U?
5-Pin, Multiple-Input, Programmable Reset IC
footprint SOT23-5_N (SOT23, 5-Leads, Body 2.9x1.6mm, Pitch 0.95mm, Lead Span 2.8mm, IPC Medium Density)
footprint SOT23-5_L (SOT23, 5-Leads, Body 2.9x1.6mm, Pitch 0.95mm, Lead Span 2.8mm, IPC High Density)
footprint SOT23-5_M (SOT23, 5-Leads, Body 2.9x1.6mm, Pitch 0.95mm, Lead Span 2.8mm, IPC Low Density)
pins: 1 RST (out), 2 GND (power), 3 RST IN1 (in), 4 RST IN2 (in), 5 VCC (power)

## MAX6311UK00D3-T
designator U?
5-Pin, Multiple-Input, Programmable Reset IC
footprint SOT23-5_N (SOT23, 5-Leads, Body 2.9x1.6mm, Pitch 0.95mm, Lead Span 2.8mm, IPC Medium Density)
footprint SOT23-5_L (SOT23, 5-Leads, Body 2.9x1.6mm, Pitch 0.95mm, Lead Span 2.8mm, IPC High Density)
footprint SOT23-5_M (SOT23, 5-Leads, Body 2.9x1.6mm, Pitch 0.95mm, Lead Span 2.8mm, IPC Low Density)
pins: 1 RST (out), 2 GND (power), 3 RST IN1 (in), 4 RST IN2 (in), 5 VCC (power)

## MAX6311UK00D4-T
designator U?
5-Pin, Multiple-Input, Programmable Reset IC
footprint SOT23-5_N (SOT23, 5-Leads, Body 2.9x1.6mm, Pitch 0.95mm, Lead Span 2.8mm, IPC Medium Density)
footprint SOT23-5_L (SOT23, 5-Leads, Body 2.9x1.6mm, Pitch 0.95mm, Lead Span 2.8mm, IPC High Density)
footprint SOT23-5_M (SOT23, 5-Leads, Body 2.9x1.6mm, Pitch 0.95mm, Lead Span 2.8mm, IPC Low Density)
pins: 1 RST (out), 2 GND (power), 3 RST IN1 (in), 4 RST IN2 (in), 5 VCC (power)

## MAX6311UK50D1-T
designator U?
5-Pin, Multiple-Input, Programmable Reset IC
footprint SOT23-5_N (SOT23, 5-Leads, Body 2.9x1.6mm, Pitch 0.95mm, Lead Span 2.8mm, IPC Medium Density)
footprint SOT23-5_L (SOT23, 5-Leads, Body 2.9x1.6mm, Pitch 0.95mm, Lead Span 2.8mm, IPC High Density)
footprint SOT23-5_M (SOT23, 5-Leads, Body 2.9x1.6mm, Pitch 0.95mm, Lead Span 2.8mm, IPC Low Density)
pins: 1 RST (out), 2 GND (power), 3 RST IN1 (in), 4 RST IN2 (in), 5 VCC (power)

## MAX6312UK25D1-T
designator U?
5-Pin, Multiple-Input, Programmable Reset IC
footprint SOT23-5_N (SOT23, 5-Leads, Body 2.9x1.6mm, Pitch 0.95mm, Lead Span 2.8mm, IPC Medium Density)
footprint SOT23-5_L (SOT23, 5-Leads, Body 2.9x1.6mm, Pitch 0.95mm, Lead Span 2.8mm, IPC High Density)
footprint SOT23-5_M (SOT23, 5-Leads, Body 2.9x1.6mm, Pitch 0.95mm, Lead Span 2.8mm, IPC Low Density)
pins: 1 RST (out), 2 GND (power), 3 ~{MR} (in), 4 RST IN (in), 5 VCC (power)

## MAX6312UK25D2-T
designator U?
5-Pin, Multiple-Input, Programmable Reset IC
footprint SOT23-5_N (SOT23, 5-Leads, Body 2.9x1.6mm, Pitch 0.95mm, Lead Span 2.8mm, IPC Medium Density)
footprint SOT23-5_L (SOT23, 5-Leads, Body 2.9x1.6mm, Pitch 0.95mm, Lead Span 2.8mm, IPC High Density)
footprint SOT23-5_M (SOT23, 5-Leads, Body 2.9x1.6mm, Pitch 0.95mm, Lead Span 2.8mm, IPC Low Density)
pins: 1 RST (out), 2 GND (power), 3 ~{MR} (in), 4 RST IN (in), 5 VCC (power)

## MAX6312UK25D3-T
designator U?
5-Pin, Multiple-Input, Programmable Reset IC
footprint SOT23-5_N (SOT23, 5-Leads, Body 2.9x1.6mm, Pitch 0.95mm, Lead Span 2.8mm, IPC Medium Density)
footprint SOT23-5_L (SOT23, 5-Leads, Body 2.9x1.6mm, Pitch 0.95mm, Lead Span 2.8mm, IPC High Density)
footprint SOT23-5_M (SOT23, 5-Leads, Body 2.9x1.6mm, Pitch 0.95mm, Lead Span 2.8mm, IPC Low Density)
pins: 1 RST (out), 2 GND (power), 3 ~{MR} (in), 4 RST IN (in), 5 VCC (power)

## MAX6312UK25D4-T
designator U?
5-Pin, Multiple-Input, Programmable Reset IC
footprint SOT23-5_N (SOT23, 5-Leads, Body 2.9x1.6mm, Pitch 0.95mm, Lead Span 2.8mm, IPC Medium Density)
footprint SOT23-5_L (SOT23, 5-Leads, Body 2.9x1.6mm, Pitch 0.95mm, Lead Span 2.8mm, IPC High Density)
footprint SOT23-5_M (SOT23, 5-Leads, Body 2.9x1.6mm, Pitch 0.95mm, Lead Span 2.8mm, IPC Low Density)
pins: 1 RST (out), 2 GND (power), 3 ~{MR} (in), 4 RST IN (in), 5 VCC (power)

## MAX6312UK26D1-T
designator U?
5-Pin, Multiple-Input, Programmable Reset IC
footprint SOT23-5_N (SOT23, 5-Leads, Body 2.9x1.6mm, Pitch 0.95mm, Lead Span 2.8mm, IPC Medium Density)
footprint SOT23-5_L (SOT23, 5-Leads, Body 2.9x1.6mm, Pitch 0.95mm, Lead Span 2.8mm, IPC High Density)
footprint SOT23-5_M (SOT23, 5-Leads, Body 2.9x1.6mm, Pitch 0.95mm, Lead Span 2.8mm, IPC Low Density)
pins: 1 RST (out), 2 GND (power), 3 ~{MR} (in), 4 RST IN (in), 5 VCC (power)

## MAX6312UK26D2-T
designator U?
5-Pin, Multiple-Input, Programmable Reset IC
footprint SOT23-5_N (SOT23, 5-Leads, Body 2.9x1.6mm, Pitch 0.95mm, Lead Span 2.8mm, IPC Medium Density)
footprint SOT23-5_L (SOT23, 5-Leads, Body 2.9x1.6mm, Pitch 0.95mm, Lead Span 2.8mm, IPC High Density)
footprint SOT23-5_M (SOT23, 5-Leads, Body 2.9x1.6mm, Pitch 0.95mm, Lead Span 2.8mm, IPC Low Density)
pins: 1 RST (out), 2 GND (power), 3 ~{MR} (in), 4 RST IN (in), 5 VCC (power)

## MAX6312UK26D3-T
designator U?
5-Pin, Multiple-Input, Programmable Reset IC
footprint SOT23-5_N (SOT23, 5-Leads, Body 2.9x1.6mm, Pitch 0.95mm, Lead Span 2.8mm, IPC Medium Density)
footprint SOT23-5_L (SOT23, 5-Leads, Body 2.9x1.6mm, Pitch 0.95mm, Lead Span 2.8mm, IPC High Density)
footprint SOT23-5_M (SOT23, 5-Leads, Body 2.9x1.6mm, Pitch 0.95mm, Lead Span 2.8mm, IPC Low Density)
pins: 1 RST (out), 2 GND (power), 3 ~{MR} (in), 4 RST IN (in), 5 VCC (power)

## MAX6312UK26D4-T
designator U?
5-Pin, Multiple-Input, Programmable Reset IC
footprint SOT23-5_N (SOT23, 5-Leads, Body 2.9x1.6mm, Pitch 0.95mm, Lead Span 2.8mm, IPC Medium Density)
footprint SOT23-5_L (SOT23, 5-Leads, Body 2.9x1.6mm, Pitch 0.95mm, Lead Span 2.8mm, IPC High Density)
footprint SOT23-5_M (SOT23, 5-Leads, Body 2.9x1.6mm, Pitch 0.95mm, Lead Span 2.8mm, IPC Low Density)
pins: 1 RST (out), 2 GND (power), 3 ~{MR} (in), 4 RST IN (in), 5 VCC (power)

## MAX6312UK27D1-T
designator U?
5-Pin, Multiple-Input, Programmable Reset IC
footprint SOT23-5_N (SOT23, 5-Leads, Body 2.9x1.6mm, Pitch 0.95mm, Lead Span 2.8mm, IPC Medium Density)
footprint SOT23-5_L (SOT23, 5-Leads, Body 2.9x1.6mm, Pitch 0.95mm, Lead Span 2.8mm, IPC High Density)
footprint SOT23-5_M (SOT23, 5-Leads, Body 2.9x1.6mm, Pitch 0.95mm, Lead Span 2.8mm, IPC Low Density)
pins: 1 RST (out), 2 GND (power), 3 ~{MR} (in), 4 RST IN (in), 5 VCC (power)

## MAX6312UK27D2-T
designator U?
5-Pin, Multiple-Input, Programmable Reset IC
footprint SOT23-5_N (SOT23, 5-Leads, Body 2.9x1.6mm, Pitch 0.95mm, Lead Span 2.8mm, IPC Medium Density)
footprint SOT23-5_L (SOT23, 5-Leads, Body 2.9x1.6mm, Pitch 0.95mm, Lead Span 2.8mm, IPC High Density)
footprint SOT23-5_M (SOT23, 5-Leads, Body 2.9x1.6mm, Pitch 0.95mm, Lead Span 2.8mm, IPC Low Density)
pins: 1 RST (out), 2 GND (power), 3 ~{MR} (in), 4 RST IN (in), 5 VCC (power)

## MAX6312UK27D3-T
designator U?
5-Pin, Multiple-Input, Programmable Reset IC
footprint SOT23-5_N (SOT23, 5-Leads, Body 2.9x1.6mm, Pitch 0.95mm, Lead Span 2.8mm, IPC Medium Density)
footprint SOT23-5_L (SOT23, 5-Leads, Body 2.9x1.6mm, Pitch 0.95mm, Lead Span 2.8mm, IPC High Density)
footprint SOT23-5_M (SOT23, 5-Leads, Body 2.9x1.6mm, Pitch 0.95mm, Lead Span 2.8mm, IPC Low Density)
pins: 1 RST (out), 2 GND (power), 3 ~{MR} (in), 4 RST IN (in), 5 VCC (power)

## MAX6312UK27D4-T
designator U?
5-Pin, Multiple-Input, Programmable Reset IC
footprint SOT23-5_N (SOT23, 5-Leads, Body 2.9x1.6mm, Pitch 0.95mm, Lead Span 2.8mm, IPC Medium Density)
footprint SOT23-5_L (SOT23, 5-Leads, Body 2.9x1.6mm, Pitch 0.95mm, Lead Span 2.8mm, IPC High Density)
footprint SOT23-5_M (SOT23, 5-Leads, Body 2.9x1.6mm, Pitch 0.95mm, Lead Span 2.8mm, IPC Low Density)
pins: 1 RST (out), 2 GND (power), 3 ~{MR} (in), 4 RST IN (in), 5 VCC (power)

## MAX6312UK28D1-T
designator U?
5-Pin, Multiple-Input, Programmable Reset IC
footprint SOT23-5_N (SOT23, 5-Leads, Body 2.9x1.6mm, Pitch 0.95mm, Lead Span 2.8mm, IPC Medium Density)
footprint SOT23-5_L (SOT23, 5-Leads, Body 2.9x1.6mm, Pitch 0.95mm, Lead Span 2.8mm, IPC High Density)
footprint SOT23-5_M (SOT23, 5-Leads, Body 2.9x1.6mm, Pitch 0.95mm, Lead Span 2.8mm, IPC Low Density)
pins: 1 RST (out), 2 GND (power), 3 ~{MR} (in), 4 RST IN (in), 5 VCC (power)

## MAX6312UK28D2-T
designator U?
5-Pin, Multiple-Input, Programmable Reset IC
footprint SOT23-5_N (SOT23, 5-Leads, Body 2.9x1.6mm, Pitch 0.95mm, Lead Span 2.8mm, IPC Medium Density)
footprint SOT23-5_L (SOT23, 5-Leads, Body 2.9x1.6mm, Pitch 0.95mm, Lead Span 2.8mm, IPC High Density)
footprint SOT23-5_M (SOT23, 5-Leads, Body 2.9x1.6mm, Pitch 0.95mm, Lead Span 2.8mm, IPC Low Density)
pins: 1 RST (out), 2 GND (power), 3 ~{MR} (in), 4 RST IN (in), 5 VCC (power)

## MAX6312UK28D3-T
designator U?
5-Pin, Multiple-Input, Programmable Reset IC
footprint SOT23-5_N (SOT23, 5-Leads, Body 2.9x1.6mm, Pitch 0.95mm, Lead Span 2.8mm, IPC Medium Density)
footprint SOT23-5_L (SOT23, 5-Leads, Body 2.9x1.6mm, Pitch 0.95mm, Lead Span 2.8mm, IPC High Density)
footprint SOT23-5_M (SOT23, 5-Leads, Body 2.9x1.6mm, Pitch 0.95mm, Lead Span 2.8mm, IPC Low Density)
pins: 1 RST (out), 2 GND (power), 3 ~{MR} (in), 4 RST IN (in), 5 VCC (power)

## MAX6312UK28D4-T
designator U?
5-Pin, Multiple-Input, Programmable Reset IC
footprint SOT23-5_N (SOT23, 5-Leads, Body 2.9x1.6mm, Pitch 0.95mm, Lead Span 2.8mm, IPC Medium Density)
footprint SOT23-5_L (SOT23, 5-Leads, Body 2.9x1.6mm, Pitch 0.95mm, Lead Span 2.8mm, IPC High Density)
footprint SOT23-5_M (SOT23, 5-Leads, Body 2.9x1.6mm, Pitch 0.95mm, Lead Span 2.8mm, IPC Low Density)
pins: 1 RST (out), 2 GND (power), 3 ~{MR} (in), 4 RST IN (in), 5 VCC (power)

## MAX6312UK29D1-T
designator U?
5-Pin, Multiple-Input, Programmable Reset IC
footprint SOT23-5_N (SOT23, 5-Leads, Body 2.9x1.6mm, Pitch 0.95mm, Lead Span 2.8mm, IPC Medium Density)
footprint SOT23-5_L (SOT23, 5-Leads, Body 2.9x1.6mm, Pitch 0.95mm, Lead Span 2.8mm, IPC High Density)
footprint SOT23-5_M (SOT23, 5-Leads, Body 2.9x1.6mm, Pitch 0.95mm, Lead Span 2.8mm, IPC Low Density)
pins: 1 RST (out), 2 GND (power), 3 ~{MR} (in), 4 RST IN (in), 5 VCC (power)

## MAX6312UK29D2-T
designator U?
5-Pin, Multiple-Input, Programmable Reset IC
footprint SOT23-5_N (SOT23, 5-Leads, Body 2.9x1.6mm, Pitch 0.95mm, Lead Span 2.8mm, IPC Medium Density)
footprint SOT23-5_L (SOT23, 5-Leads, Body 2.9x1.6mm, Pitch 0.95mm, Lead Span 2.8mm, IPC High Density)
footprint SOT23-5_M (SOT23, 5-Leads, Body 2.9x1.6mm, Pitch 0.95mm, Lead Span 2.8mm, IPC Low Density)
pins: 1 RST (out), 2 GND (power), 3 ~{MR} (in), 4 RST IN (in), 5 VCC (power)

## MAX6312UK29D3-T
designator U?
5-Pin, Multiple-Input, Programmable Reset IC
footprint SOT23-5_N (SOT23, 5-Leads, Body 2.9x1.6mm, Pitch 0.95mm, Lead Span 2.8mm, IPC Medium Density)
footprint SOT23-5_L (SOT23, 5-Leads, Body 2.9x1.6mm, Pitch 0.95mm, Lead Span 2.8mm, IPC High Density)
footprint SOT23-5_M (SOT23, 5-Leads, Body 2.9x1.6mm, Pitch 0.95mm, Lead Span 2.8mm, IPC Low Density)
pins: 1 RST (out), 2 GND (power), 3 ~{MR} (in), 4 RST IN (in), 5 VCC (power)

## MAX6312UK29D4-T
designator U?
5-Pin, Multiple-Input, Programmable Reset IC
footprint SOT23-5_N (SOT23, 5-Leads, Body 2.9x1.6mm, Pitch 0.95mm, Lead Span 2.8mm, IPC Medium Density)
footprint SOT23-5_L (SOT23, 5-Leads, Body 2.9x1.6mm, Pitch 0.95mm, Lead Span 2.8mm, IPC High Density)
footprint SOT23-5_M (SOT23, 5-Leads, Body 2.9x1.6mm, Pitch 0.95mm, Lead Span 2.8mm, IPC Low Density)
pins: 1 RST (out), 2 GND (power), 3 ~{MR} (in), 4 RST IN (in), 5 VCC (power)

## MAX6312UK30D1-T
designator U?
5-Pin, Multiple-Input, Programmable Reset IC
footprint SOT23-5_N (SOT23, 5-Leads, Body 2.9x1.6mm, Pitch 0.95mm, Lead Span 2.8mm, IPC Medium Density)
footprint SOT23-5_L (SOT23, 5-Leads, Body 2.9x1.6mm, Pitch 0.95mm, Lead Span 2.8mm, IPC High Density)
footprint SOT23-5_M (SOT23, 5-Leads, Body 2.9x1.6mm, Pitch 0.95mm, Lead Span 2.8mm, IPC Low Density)
pins: 1 RST (out), 2 GND (power), 3 ~{MR} (in), 4 RST IN (in), 5 VCC (power)

## MAX6312UK30D2-T
designator U?
5-Pin, Multiple-Input, Programmable Reset IC
footprint SOT23-5_N (SOT23, 5-Leads, Body 2.9x1.6mm, Pitch 0.95mm, Lead Span 2.8mm, IPC Medium Density)
footprint SOT23-5_L (SOT23, 5-Leads, Body 2.9x1.6mm, Pitch 0.95mm, Lead Span 2.8mm, IPC High Density)
footprint SOT23-5_M (SOT23, 5-Leads, Body 2.9x1.6mm, Pitch 0.95mm, Lead Span 2.8mm, IPC Low Density)
pins: 1 RST (out), 2 GND (power), 3 ~{MR} (in), 4 RST IN (in), 5 VCC (power)

## MAX6312UK30D3-T
designator U?
5-Pin, Multiple-Input, Programmable Reset IC
footprint SOT23-5_N (SOT23, 5-Leads, Body 2.9x1.6mm, Pitch 0.95mm, Lead Span 2.8mm, IPC Medium Density)
footprint SOT23-5_L (SOT23, 5-Leads, Body 2.9x1.6mm, Pitch 0.95mm, Lead Span 2.8mm, IPC High Density)
footprint SOT23-5_M (SOT23, 5-Leads, Body 2.9x1.6mm, Pitch 0.95mm, Lead Span 2.8mm, IPC Low Density)
pins: 1 RST (out), 2 GND (power), 3 ~{MR} (in), 4 RST IN (in), 5 VCC (power)

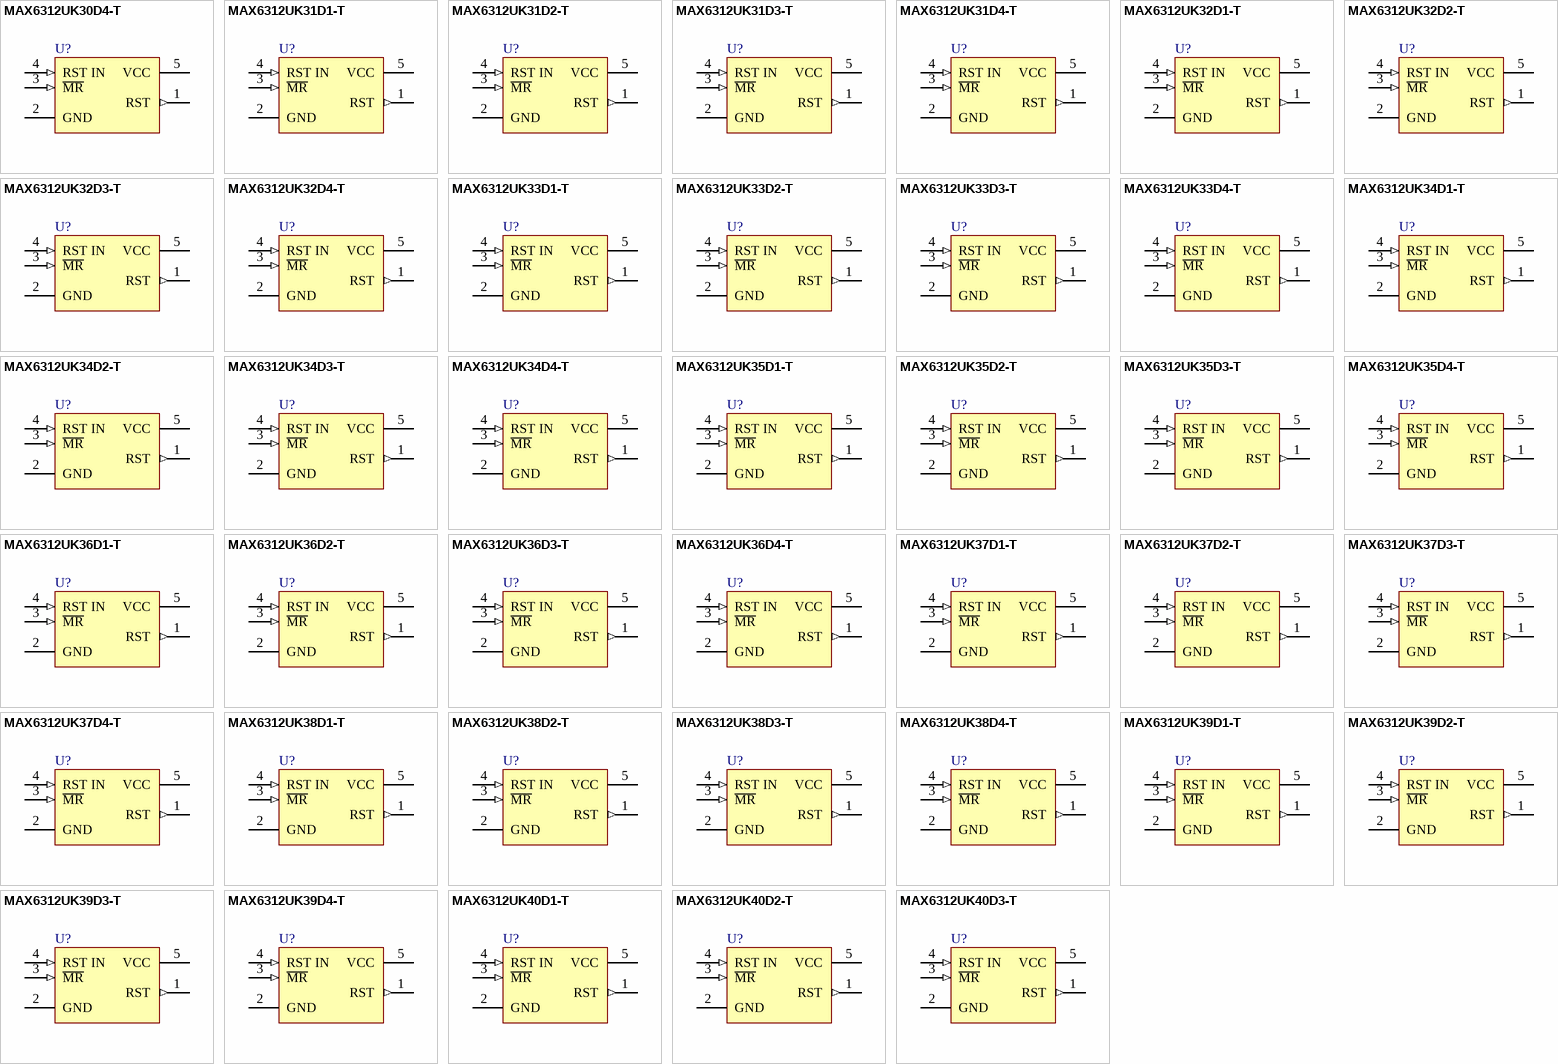
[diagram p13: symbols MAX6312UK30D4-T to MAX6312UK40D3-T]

## MAX6312UK30D4-T
designator U?
5-Pin, Multiple-Input, Programmable Reset IC
footprint SOT23-5_N (SOT23, 5-Leads, Body 2.9x1.6mm, Pitch 0.95mm, Lead Span 2.8mm, IPC Medium Density)
footprint SOT23-5_L (SOT23, 5-Leads, Body 2.9x1.6mm, Pitch 0.95mm, Lead Span 2.8mm, IPC High Density)
footprint SOT23-5_M (SOT23, 5-Leads, Body 2.9x1.6mm, Pitch 0.95mm, Lead Span 2.8mm, IPC Low Density)
pins: 1 RST (out), 2 GND (power), 3 ~{MR} (in), 4 RST IN (in), 5 VCC (power)

## MAX6312UK31D1-T
designator U?
5-Pin, Multiple-Input, Programmable Reset IC
footprint SOT23-5_N (SOT23, 5-Leads, Body 2.9x1.6mm, Pitch 0.95mm, Lead Span 2.8mm, IPC Medium Density)
footprint SOT23-5_L (SOT23, 5-Leads, Body 2.9x1.6mm, Pitch 0.95mm, Lead Span 2.8mm, IPC High Density)
footprint SOT23-5_M (SOT23, 5-Leads, Body 2.9x1.6mm, Pitch 0.95mm, Lead Span 2.8mm, IPC Low Density)
pins: 1 RST (out), 2 GND (power), 3 ~{MR} (in), 4 RST IN (in), 5 VCC (power)

## MAX6312UK31D2-T
designator U?
5-Pin, Multiple-Input, Programmable Reset IC
footprint SOT23-5_N (SOT23, 5-Leads, Body 2.9x1.6mm, Pitch 0.95mm, Lead Span 2.8mm, IPC Medium Density)
footprint SOT23-5_L (SOT23, 5-Leads, Body 2.9x1.6mm, Pitch 0.95mm, Lead Span 2.8mm, IPC High Density)
footprint SOT23-5_M (SOT23, 5-Leads, Body 2.9x1.6mm, Pitch 0.95mm, Lead Span 2.8mm, IPC Low Density)
pins: 1 RST (out), 2 GND (power), 3 ~{MR} (in), 4 RST IN (in), 5 VCC (power)

## MAX6312UK31D3-T
designator U?
5-Pin, Multiple-Input, Programmable Reset IC
footprint SOT23-5_N (SOT23, 5-Leads, Body 2.9x1.6mm, Pitch 0.95mm, Lead Span 2.8mm, IPC Medium Density)
footprint SOT23-5_L (SOT23, 5-Leads, Body 2.9x1.6mm, Pitch 0.95mm, Lead Span 2.8mm, IPC High Density)
footprint SOT23-5_M (SOT23, 5-Leads, Body 2.9x1.6mm, Pitch 0.95mm, Lead Span 2.8mm, IPC Low Density)
pins: 1 RST (out), 2 GND (power), 3 ~{MR} (in), 4 RST IN (in), 5 VCC (power)

## MAX6312UK31D4-T
designator U?
5-Pin, Multiple-Input, Programmable Reset IC
footprint SOT23-5_N (SOT23, 5-Leads, Body 2.9x1.6mm, Pitch 0.95mm, Lead Span 2.8mm, IPC Medium Density)
footprint SOT23-5_L (SOT23, 5-Leads, Body 2.9x1.6mm, Pitch 0.95mm, Lead Span 2.8mm, IPC High Density)
footprint SOT23-5_M (SOT23, 5-Leads, Body 2.9x1.6mm, Pitch 0.95mm, Lead Span 2.8mm, IPC Low Density)
pins: 1 RST (out), 2 GND (power), 3 ~{MR} (in), 4 RST IN (in), 5 VCC (power)

## MAX6312UK32D1-T
designator U?
5-Pin, Multiple-Input, Programmable Reset IC
footprint SOT23-5_N (SOT23, 5-Leads, Body 2.9x1.6mm, Pitch 0.95mm, Lead Span 2.8mm, IPC Medium Density)
footprint SOT23-5_L (SOT23, 5-Leads, Body 2.9x1.6mm, Pitch 0.95mm, Lead Span 2.8mm, IPC High Density)
footprint SOT23-5_M (SOT23, 5-Leads, Body 2.9x1.6mm, Pitch 0.95mm, Lead Span 2.8mm, IPC Low Density)
pins: 1 RST (out), 2 GND (power), 3 ~{MR} (in), 4 RST IN (in), 5 VCC (power)

## MAX6312UK32D2-T
designator U?
5-Pin, Multiple-Input, Programmable Reset IC
footprint SOT23-5_N (SOT23, 5-Leads, Body 2.9x1.6mm, Pitch 0.95mm, Lead Span 2.8mm, IPC Medium Density)
footprint SOT23-5_L (SOT23, 5-Leads, Body 2.9x1.6mm, Pitch 0.95mm, Lead Span 2.8mm, IPC High Density)
footprint SOT23-5_M (SOT23, 5-Leads, Body 2.9x1.6mm, Pitch 0.95mm, Lead Span 2.8mm, IPC Low Density)
pins: 1 RST (out), 2 GND (power), 3 ~{MR} (in), 4 RST IN (in), 5 VCC (power)

## MAX6312UK32D3-T
designator U?
5-Pin, Multiple-Input, Programmable Reset IC
footprint SOT23-5_N (SOT23, 5-Leads, Body 2.9x1.6mm, Pitch 0.95mm, Lead Span 2.8mm, IPC Medium Density)
footprint SOT23-5_L (SOT23, 5-Leads, Body 2.9x1.6mm, Pitch 0.95mm, Lead Span 2.8mm, IPC High Density)
footprint SOT23-5_M (SOT23, 5-Leads, Body 2.9x1.6mm, Pitch 0.95mm, Lead Span 2.8mm, IPC Low Density)
pins: 1 RST (out), 2 GND (power), 3 ~{MR} (in), 4 RST IN (in), 5 VCC (power)

## MAX6312UK32D4-T
designator U?
5-Pin, Multiple-Input, Programmable Reset IC
footprint SOT23-5_N (SOT23, 5-Leads, Body 2.9x1.6mm, Pitch 0.95mm, Lead Span 2.8mm, IPC Medium Density)
footprint SOT23-5_L (SOT23, 5-Leads, Body 2.9x1.6mm, Pitch 0.95mm, Lead Span 2.8mm, IPC High Density)
footprint SOT23-5_M (SOT23, 5-Leads, Body 2.9x1.6mm, Pitch 0.95mm, Lead Span 2.8mm, IPC Low Density)
pins: 1 RST (out), 2 GND (power), 3 ~{MR} (in), 4 RST IN (in), 5 VCC (power)

## MAX6312UK33D1-T
designator U?
5-Pin, Multiple-Input, Programmable Reset IC
footprint SOT23-5_N (SOT23, 5-Leads, Body 2.9x1.6mm, Pitch 0.95mm, Lead Span 2.8mm, IPC Medium Density)
footprint SOT23-5_L (SOT23, 5-Leads, Body 2.9x1.6mm, Pitch 0.95mm, Lead Span 2.8mm, IPC High Density)
footprint SOT23-5_M (SOT23, 5-Leads, Body 2.9x1.6mm, Pitch 0.95mm, Lead Span 2.8mm, IPC Low Density)
pins: 1 RST (out), 2 GND (power), 3 ~{MR} (in), 4 RST IN (in), 5 VCC (power)

## MAX6312UK33D2-T
designator U?
5-Pin, Multiple-Input, Programmable Reset IC
footprint SOT23-5_N (SOT23, 5-Leads, Body 2.9x1.6mm, Pitch 0.95mm, Lead Span 2.8mm, IPC Medium Density)
footprint SOT23-5_L (SOT23, 5-Leads, Body 2.9x1.6mm, Pitch 0.95mm, Lead Span 2.8mm, IPC High Density)
footprint SOT23-5_M (SOT23, 5-Leads, Body 2.9x1.6mm, Pitch 0.95mm, Lead Span 2.8mm, IPC Low Density)
pins: 1 RST (out), 2 GND (power), 3 ~{MR} (in), 4 RST IN (in), 5 VCC (power)

## MAX6312UK33D3-T
designator U?
5-Pin, Multiple-Input, Programmable Reset IC
footprint SOT23-5_N (SOT23, 5-Leads, Body 2.9x1.6mm, Pitch 0.95mm, Lead Span 2.8mm, IPC Medium Density)
footprint SOT23-5_L (SOT23, 5-Leads, Body 2.9x1.6mm, Pitch 0.95mm, Lead Span 2.8mm, IPC High Density)
footprint SOT23-5_M (SOT23, 5-Leads, Body 2.9x1.6mm, Pitch 0.95mm, Lead Span 2.8mm, IPC Low Density)
pins: 1 RST (out), 2 GND (power), 3 ~{MR} (in), 4 RST IN (in), 5 VCC (power)

## MAX6312UK33D4-T
designator U?
5-Pin, Multiple-Input, Programmable Reset IC
footprint SOT23-5_N (SOT23, 5-Leads, Body 2.9x1.6mm, Pitch 0.95mm, Lead Span 2.8mm, IPC Medium Density)
footprint SOT23-5_L (SOT23, 5-Leads, Body 2.9x1.6mm, Pitch 0.95mm, Lead Span 2.8mm, IPC High Density)
footprint SOT23-5_M (SOT23, 5-Leads, Body 2.9x1.6mm, Pitch 0.95mm, Lead Span 2.8mm, IPC Low Density)
pins: 1 RST (out), 2 GND (power), 3 ~{MR} (in), 4 RST IN (in), 5 VCC (power)

## MAX6312UK34D1-T
designator U?
5-Pin, Multiple-Input, Programmable Reset IC
footprint SOT23-5_N (SOT23, 5-Leads, Body 2.9x1.6mm, Pitch 0.95mm, Lead Span 2.8mm, IPC Medium Density)
footprint SOT23-5_L (SOT23, 5-Leads, Body 2.9x1.6mm, Pitch 0.95mm, Lead Span 2.8mm, IPC High Density)
footprint SOT23-5_M (SOT23, 5-Leads, Body 2.9x1.6mm, Pitch 0.95mm, Lead Span 2.8mm, IPC Low Density)
pins: 1 RST (out), 2 GND (power), 3 ~{MR} (in), 4 RST IN (in), 5 VCC (power)

## MAX6312UK34D2-T
designator U?
5-Pin, Multiple-Input, Programmable Reset IC
footprint SOT23-5_N (SOT23, 5-Leads, Body 2.9x1.6mm, Pitch 0.95mm, Lead Span 2.8mm, IPC Medium Density)
footprint SOT23-5_L (SOT23, 5-Leads, Body 2.9x1.6mm, Pitch 0.95mm, Lead Span 2.8mm, IPC High Density)
footprint SOT23-5_M (SOT23, 5-Leads, Body 2.9x1.6mm, Pitch 0.95mm, Lead Span 2.8mm, IPC Low Density)
pins: 1 RST (out), 2 GND (power), 3 ~{MR} (in), 4 RST IN (in), 5 VCC (power)

## MAX6312UK34D3-T
designator U?
5-Pin, Multiple-Input, Programmable Reset IC
footprint SOT23-5_N (SOT23, 5-Leads, Body 2.9x1.6mm, Pitch 0.95mm, Lead Span 2.8mm, IPC Medium Density)
footprint SOT23-5_L (SOT23, 5-Leads, Body 2.9x1.6mm, Pitch 0.95mm, Lead Span 2.8mm, IPC High Density)
footprint SOT23-5_M (SOT23, 5-Leads, Body 2.9x1.6mm, Pitch 0.95mm, Lead Span 2.8mm, IPC Low Density)
pins: 1 RST (out), 2 GND (power), 3 ~{MR} (in), 4 RST IN (in), 5 VCC (power)

## MAX6312UK34D4-T
designator U?
5-Pin, Multiple-Input, Programmable Reset IC
footprint SOT23-5_N (SOT23, 5-Leads, Body 2.9x1.6mm, Pitch 0.95mm, Lead Span 2.8mm, IPC Medium Density)
footprint SOT23-5_L (SOT23, 5-Leads, Body 2.9x1.6mm, Pitch 0.95mm, Lead Span 2.8mm, IPC High Density)
footprint SOT23-5_M (SOT23, 5-Leads, Body 2.9x1.6mm, Pitch 0.95mm, Lead Span 2.8mm, IPC Low Density)
pins: 1 RST (out), 2 GND (power), 3 ~{MR} (in), 4 RST IN (in), 5 VCC (power)

## MAX6312UK35D1-T
designator U?
5-Pin, Multiple-Input, Programmable Reset IC
footprint SOT23-5_N (SOT23, 5-Leads, Body 2.9x1.6mm, Pitch 0.95mm, Lead Span 2.8mm, IPC Medium Density)
footprint SOT23-5_L (SOT23, 5-Leads, Body 2.9x1.6mm, Pitch 0.95mm, Lead Span 2.8mm, IPC High Density)
footprint SOT23-5_M (SOT23, 5-Leads, Body 2.9x1.6mm, Pitch 0.95mm, Lead Span 2.8mm, IPC Low Density)
pins: 1 RST (out), 2 GND (power), 3 ~{MR} (in), 4 RST IN (in), 5 VCC (power)

## MAX6312UK35D2-T
designator U?
5-Pin, Multiple-Input, Programmable Reset IC
footprint SOT23-5_N (SOT23, 5-Leads, Body 2.9x1.6mm, Pitch 0.95mm, Lead Span 2.8mm, IPC Medium Density)
footprint SOT23-5_L (SOT23, 5-Leads, Body 2.9x1.6mm, Pitch 0.95mm, Lead Span 2.8mm, IPC High Density)
footprint SOT23-5_M (SOT23, 5-Leads, Body 2.9x1.6mm, Pitch 0.95mm, Lead Span 2.8mm, IPC Low Density)
pins: 1 RST (out), 2 GND (power), 3 ~{MR} (in), 4 RST IN (in), 5 VCC (power)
